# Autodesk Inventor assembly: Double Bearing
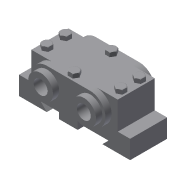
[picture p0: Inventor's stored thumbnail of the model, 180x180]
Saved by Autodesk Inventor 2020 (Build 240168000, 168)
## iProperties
Created: 2002-02
Part Number: Double Bearing
Document SubType Name: Assembly
Designer: ***
Control State: 0
Master: False
Checked Out: False
Shininess: 64.0
Length Units: 11269
Angle Units: 11279
Time Units: 11290
Mass Units: 11283
Length Display Precision: 3
Angle Display Precision: 2
Density: 0.0
Volumn: 0.0
Area: 0.0
PropertySet Name: Model Information
Author: ***
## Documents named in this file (5)
- D:\Autodesk Inventor_2020\Resources\Resources\Inventor_2019_Exr\Inventor_2019_Exr\c11_inv_2018_exr\c11_Inv\c11_exr01_inv\Double Bearing Assembly\Double Bearing.iam
- D:\Autodesk Inventor_2020\Resources\Resources\Inventor_2019_Exr\Inventor_2019_Exr\c11_inv_2018_exr\c11_Inv\c11_exr01_inv\Double Bearing Assembly\Base.ipt
- D:\Autodesk Inventor_2020\Resources\Resources\Inventor_2019_Exr\Inventor_2019_Exr\c11_inv_2018_exr\c11_Inv\c11_exr01_inv\Double Bearing Assembly\Cap.ipt
- D:\Autodesk Inventor_2020\Resources\Resources\Inventor_2019_Exr\Inventor_2019_Exr\c11_inv_2018_exr\c11_Inv\c11_exr01_inv\Double Bearing Assembly\Bushing.ipt
- D:\Autodesk Inventor_2020\Resources\Resources\Inventor_2019_Exr\Inventor_2019_Exr\c11_inv_2018_exr\c11_Inv\c11_exr01_inv\Double Bearing Assembly\Bolt.ipt
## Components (10 placed, 4 different names)
1. Base:1 — Insert:1, Insert:2
2. Cap:1 — Insert:1, Insert:2, Insert:3, Insert:4, Insert:5, Insert:6
3. Bushing:1 — Insert:3
4. Bushing:2 — Insert:4
5. Bolt:1 — Insert:5
6. Bolt:6
7. Bolt:7
8. Bolt:8
9. Bolt:5 — Insert:6
10. Bolt:9
## Component patterns: Component Pattern 1 (4 elements), Component Pattern 2 (2 elements)
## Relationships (6: Insert 6)
- Insert:1: Base:1 ↔ Cap:1
- Insert:2: Base:1 ↔ Cap:1
- Insert:3: Cap:1 ↔ Bushing:1
- Insert:4: Cap:1 ↔ Bushing:2
- Insert:5: Cap:1 ↔ Bolt:1
- Insert:6: Cap:1 ↔ Bolt:5
